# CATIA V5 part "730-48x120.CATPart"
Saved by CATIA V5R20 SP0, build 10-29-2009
Part number: 730-48x120
Definition: NONE
Nomenclature: 730-48x120
Source: Unknown
Description: 730-48x120
Bounding box of the stored display mesh (mm): x -28 to 28, y -27.5 to 27.5, z 0 to 120
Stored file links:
  C:\Users\Utente\Desktop\IO LAVORO\3D X SITO CF\X SITO\730\730-48x120.CATPart
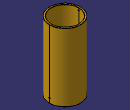
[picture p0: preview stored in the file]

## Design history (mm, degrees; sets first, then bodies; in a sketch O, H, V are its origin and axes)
Body1 "730-48x120" (main body)
  Solid1: solid without history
